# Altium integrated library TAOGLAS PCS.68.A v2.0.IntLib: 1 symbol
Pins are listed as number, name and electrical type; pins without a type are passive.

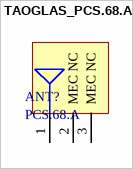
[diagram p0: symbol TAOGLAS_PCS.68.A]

## TAOGLAS_PCS.68.A
designator ANT?, comment PCS.68.A
Reach Low Profile Wideband 5G/4G PCB SMD Antenna; ComponentLibStatus: Created; MFG: Taoglas
footprint TAOGLAS_PCS.68.A (Reach Low Profile Wideband 5G/4G PCB SMD Antenna)
pins: 1 RF Feed, 2 MEC NC, 3 MEC NC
